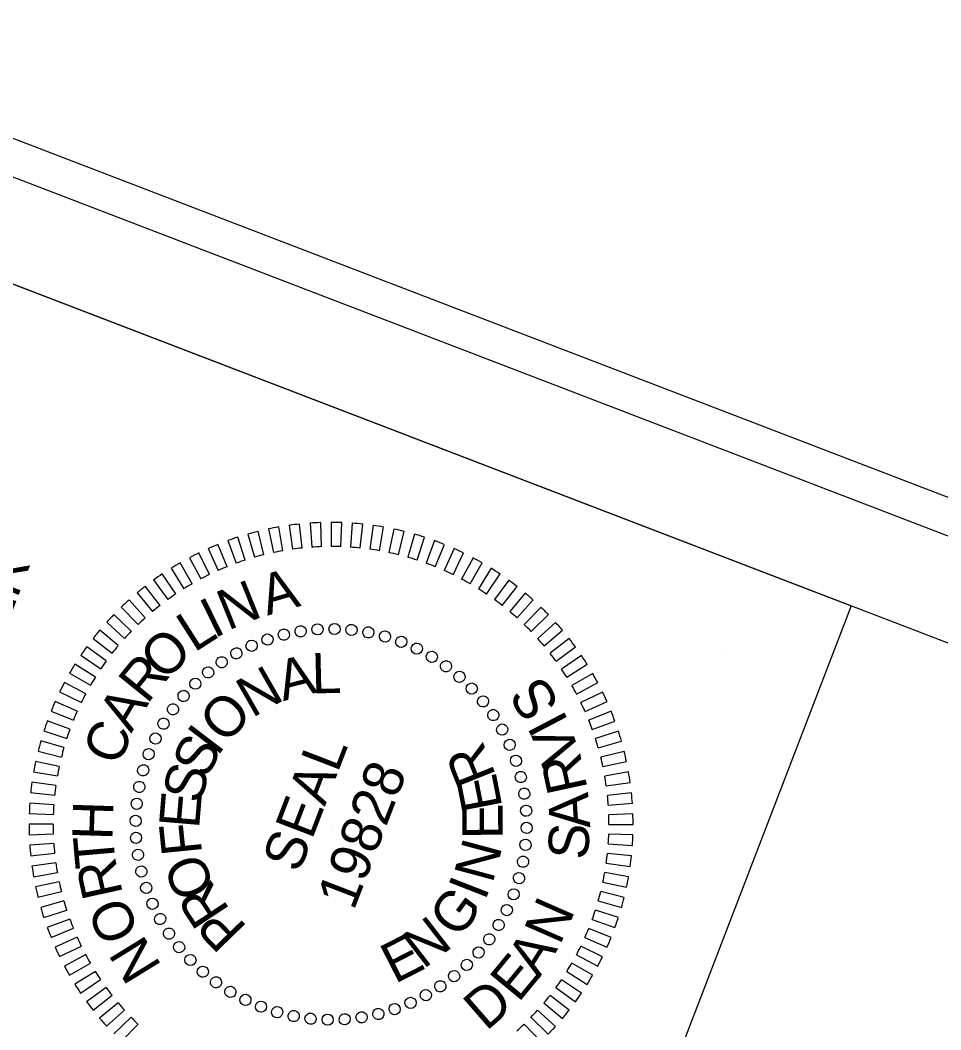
# Model space of a CAD drawing. Extents: x 1015221 to 1064345, y 619216 to 647967.
# Drawn here: x 1034182 to 1035103, y 641647 to 642657 of the extents above; entities that cross this region are included whole.
import ezdxf

# ---------------------------------------------------------------- set-up
doc = ezdxf.new("R2010")
doc.units = 0
for name, color, linetype in [('Scratch_Level_0', 7, 'Continuous'), ('Sheet PE Seal Cell', 7, 'Continuous'), ('Sheet Plan CELL', 7, 'Continuous'), ('Sheet Plot Border Inside CELL', 7, 'Continuous'), ('Sheet Plot Border Outside CELL', 7, 'Continuous')]:
    doc.layers.add(name, color=color, linetype=linetype)

msp = doc.modelspace()

# ---------------------------------------------------------------- linework, layer by layer
at = {"layer": 'Scratch_Level_0'}
for p, q in [((1034883.3, 642026.4), (1034883.3, 642026.4)), ((1034492.9, 641852.7), (1034492.9, 641852.7))]:
    msp.add_line(p, q, dxfattribs=at)
at = {"layer": 'Sheet PE Seal Cell'}
for p, q in [((1034444.7, 642126.5), (1034440.6, 642150.3)), ((1034451, 642151.9), (1034454.3, 642128)), ((1034464, 642129.2), (1034461.4, 642153.2)), ((1034471.9, 642154.1), (1034473.6, 642130)), ((1034483.3, 642130.5), (1034482.5, 642154.7)), ((1034493, 642154.9), (1034493, 642130.7)), ((1034502.7, 642130.5), (1034503.6, 642154.7)), ((1034514.1, 642154.1), (1034512.4, 642130)), ((1034522.1, 642129.2), (1034524.6, 642153.2)), ((1034535.1, 642151.9), (1034531.7, 642128)), ((1034541.3, 642126.5), (1034545.5, 642150.3)), ((1034407.1, 642117.1), (1034399.6, 642140.1)), ((1034409.7, 642143.2), (1034416.4, 642119.9)), ((1034425.8, 642122.5), (1034419.9, 642145.9)), ((1034430.2, 642148.3), (1034435.2, 642124.6)), ((1034555.8, 642148.2), (1034550.8, 642124.6)), ((1034560.3, 642122.4), (1034566.1, 642145.9)), ((1034576.3, 642143.1), (1034569.6, 642119.9)), ((1034578.9, 642117.1), (1034586.4, 642140)), ((1034388.9, 642110.5), (1034379.8, 642132.9)), ((1034389.7, 642136.7), (1034397.9, 642114)), ((1034596.4, 642136.6), (1034588.1, 642113.9)), ((1034597.1, 642110.4), (1034606.2, 642132.8)), ((1034351.2, 642119.5), (1034362.5, 642098.2)), ((1034371.2, 642102.6), (1034360.6, 642124.3)), ((1034370.1, 642128.8), (1034379.9, 642106.7)), ((1034615.9, 642128.7), (1034606.1, 642106.6)), ((1034614.9, 642102.5), (1034625.5, 642124.2)), ((1034634.9, 642119.5), (1034623.5, 642098.1)), ((1034332.9, 642109), (1034345.7, 642088.5)), ((1034354, 642093.5), (1034341.9, 642114.4)), ((1034632, 642093.4), (1034644.1, 642114.3)), ((1034653.1, 642108.9), (1034640.3, 642088.4)), ((1034337.6, 642083.2), (1034324, 642103.3)), ((1034648.4, 642083.1), (1034662, 642103.2)), ((1034321.9, 642071.8), (1034307, 642090.9)), ((1034315.4, 642097.2), (1034329.6, 642077.7)), ((1034670.6, 642097.1), (1034656.4, 642077.6)), ((1034664.1, 642071.7), (1034679, 642090.8)), ((1034298.8, 642084.2), (1034314.3, 642065.7)), ((1034687.2, 642084.1), (1034671.7, 642065.6)), ((1034283.1, 642070.1), (1034299.9, 642052.7)), ((1034307, 642059.3), (1034290.8, 642077.3)), ((1034679, 642059.2), (1034695.2, 642077.2)), ((1034702.9, 642070), (1034686.1, 642052.6)), ((1034293, 642045.9), (1034275.6, 642062.7)), ((1034692.9, 642045.8), (1034710.3, 642062.5)), ((1034268.5, 642055), (1034286.4, 642038.8)), ((1034496.3, 642048.5), (1034496.3, 642048.5)), ((1034717.5, 642054.8), (1034699.6, 642038.7)), ((1034254.9, 642038.8), (1034273.9, 642023.9)), ((1034280, 642031.5), (1034261.5, 642047)), ((1034429.2, 642038), (1034429.2, 642038)), ((1034445.6, 642042.6), (1034445.6, 642042.6)), ((1034462.4, 642046.1), (1034462.4, 642046.1)), ((1034479.4, 642047.9), (1034479.4, 642047.9)), ((1034513.4, 642047.4), (1034513.4, 642047.4)), ((1034530.3, 642044.7), (1034530.3, 642044.7)), ((1034546.8, 642040.8), (1034546.8, 642040.8)), ((1034705.9, 642031.3), (1034724.4, 642046.9)), ((1034731.1, 642038.7), (1034712, 642023.8)), ((1034268.1, 642016.2), (1034248.5, 642030.4)), ((1034413.4, 642031.6), (1034413.4, 642031.6)), ((1034563.1, 642035.4), (1034563.1, 642035.4)), ((1034578.9, 642028.5), (1034578.9, 642028.5)), ((1034717.9, 642016), (1034737.4, 642030.2)), ((1034242.5, 642021.8), (1034262.5, 642008.2)), ((1034398, 642024.1), (1034398, 642024.1)), ((1034593.7, 642020.3), (1034593.7, 642020.3)), ((1034743.5, 642021.6), (1034723.4, 642008.1)), ((1034257.2, 642000.1), (1034236.7, 642012.9)), ((1034383.6, 642015), (1034383.6, 642015)), ((1034608.1, 642011), (1034608.1, 642011)), ((1034728.7, 642000), (1034749.2, 642012.8)), ((1034231.3, 642003.9), (1034252.2, 641991.8)), ((1034369.7, 642004.9), (1034369.7, 642004.9)), ((1034621.5, 642000.4), (1034621.5, 642000.4)), ((1034754.6, 642003.7), (1034733.7, 641991.6)), ((1034247.5, 641983.3), (1034226.2, 641994.6)), ((1034357, 641993.5), (1034357, 641993.5)), ((1034633.7, 641988.7), (1034633.7, 641988.7)), ((1034738.4, 641983.1), (1034759.8, 641994.5)), ((1034221.4, 641985.3), (1034243.1, 641974.6)), ((1034345.2, 641981.3), (1034345.2, 641981.3)), ((1034764.5, 641985.1), (1034742.8, 641974.5)), ((1034239, 641965.9), (1034216.9, 641975.7)), ((1034334.6, 641967.8), (1034334.6, 641967.8)), ((1034645.1, 641975.9), (1034645.1, 641975.9)), ((1034746.9, 641965.7), (1034769, 641975.5)), ((1034212.8, 641966), (1034235.2, 641956.9)), ((1034655.2, 641962), (1034655.2, 641962)), ((1034773.1, 641965.8), (1034750.7, 641956.8)), ((1034231.7, 641947.9), (1034209, 641956.1)), ((1034325.3, 641953.5), (1034325.3, 641953.5)), ((1034664.3, 641947.7), (1034664.3, 641947.7)), ((1034754.2, 641947.7), (1034776.9, 641956)), ((1034205.6, 641946.2), (1034228.6, 641938.7)), ((1034317.1, 641938.6), (1034317.1, 641938.6)), ((1034780.3, 641946), (1034757.3, 641938.5)), ((1034225.7, 641929.4), (1034202.5, 641936.1)), ((1034671.8, 641932.3), (1034671.8, 641932.3)), ((1034760.2, 641929.3), (1034783.4, 641935.9)), ((1034199.8, 641925.9), (1034223.2, 641920)), ((1034310.2, 641922.9), (1034310.2, 641922.9)), ((1034786.1, 641925.7), (1034762.7, 641919.9)), ((1034221, 641910.6), (1034197.4, 641915.6)), ((1034304.8, 641906.6), (1034304.8, 641906.6)), ((1034678.2, 641916.4), (1034678.2, 641916.4)), ((1034764.8, 641910.4), (1034788.5, 641915.4)), ((1034195.4, 641905.3), (1034219.2, 641901.1)), ((1034682.8, 641900.1), (1034682.8, 641900.1)), ((1034790.5, 641905.1), (1034766.7, 641900.9)), ((1034217.7, 641891.5), (1034193.7, 641894.9)), ((1034301, 641890.1), (1034301, 641890.1)), ((1034768.2, 641891.3), (1034792.2, 641894.7)), ((1034192.4, 641884.4), (1034216.5, 641881.9)), ((1034686.3, 641883.2), (1034686.3, 641883.2)), ((1034793.4, 641884.2), (1034769.4, 641881.7)), ((1034215.6, 641872.2), (1034191.5, 641873.9)), ((1034298.2, 641873.2), (1034298.2, 641873.2)), ((1034688.2, 641866.3), (1034688.2, 641866.3)), ((1034770.2, 641872), (1034794.3, 641873.7)), ((1034191, 641863.4), (1034215.1, 641862.5)), ((1034297.1, 641856.1), (1034297.1, 641856.1)), ((1034794.9, 641863.2), (1034770.7, 641862.3)), ((1034215, 641852.8), (1034190.8, 641852.8)), ((1034688.8, 641849.3), (1034688.8, 641849.3)), ((1034770.9, 641852.6), (1034795.1, 641852.6)), ((1034191, 641842.3), (1034215.1, 641843.1)), ((1034297.7, 641839.2), (1034297.7, 641839.2)), ((1034794.9, 641842.1), (1034770.7, 641842.9)), ((1034215.6, 641833.4), (1034191.5, 641831.7)), ((1034687.6, 641832.2), (1034687.6, 641832.2)), ((1034770.2, 641833.2), (1034794.3, 641831.6)), ((1034192.4, 641821.2), (1034216.5, 641823.7)), ((1034299.5, 641822.2), (1034299.5, 641822.2)), ((1034793.4, 641821), (1034769.4, 641823.6)), ((1034217.7, 641814.1), (1034193.7, 641810.8)), ((1034684.9, 641815.3), (1034684.9, 641815.3)), ((1034768.2, 641813.9), (1034792.1, 641810.6)), ((1034195.4, 641800.3), (1034219.2, 641804.5)), ((1034303.1, 641805.4), (1034303.1, 641805.4)), ((1034681, 641798.8), (1034681, 641798.8)), ((1034790.5, 641800.2), (1034766.7, 641804.4)), ((1034221, 641795), (1034197.4, 641790)), ((1034199.7, 641779.7), (1034223.2, 641785.5)), ((1034307.7, 641789), (1034307.7, 641789)), ((1034786.1, 641779.5), (1034762.6, 641785.4)), ((1034764.8, 641794.8), (1034788.5, 641789.8)), ((1034225.7, 641776.2), (1034202.5, 641769.5)), ((1034675.6, 641782.5), (1034675.6, 641782.5)), ((1034760.1, 641776), (1034783.3, 641769.3)), ((1034205.5, 641759.4), (1034228.5, 641766.9)), ((1034314.1, 641773.2), (1034314.1, 641773.2)), ((1034668.7, 641766.8), (1034668.7, 641766.8)), ((1034780.3, 641759.3), (1034757.3, 641766.7)), ((1034231.7, 641757.7), (1034209, 641749.5)), ((1034321.6, 641757.8), (1034321.6, 641757.8)), ((1034754.1, 641757.6), (1034776.8, 641749.3)), ((1034212.8, 641739.6), (1034235.2, 641748.7)), ((1034660.5, 641752), (1034660.5, 641752)), ((1034773, 641739.4), (1034750.6, 641748.5)), ((1034239, 641739.7), (1034216.9, 641729.9)), ((1034330.7, 641743.4), (1034330.7, 641743.4)), ((1034651.3, 641737.6), (1034651.3, 641737.6)), ((1034746.8, 641739.6), (1034768.9, 641729.7)), ((1034221.3, 641720.3), (1034243.1, 641730.9)), ((1034340.8, 641729.5), (1034340.8, 641729.5)), ((1034764.5, 641720.2), (1034742.7, 641730.8)), ((1034247.5, 641722.3), (1034226.1, 641710.9)), ((1034352.2, 641716.8), (1034352.2, 641716.8)), ((1034640.7, 641724.1), (1034640.7, 641724.1)), ((1034738.3, 641722.1), (1034759.7, 641710.8)), ((1034231.2, 641701.7), (1034252.2, 641713.8)), ((1034257.2, 641705.5), (1034236.6, 641692.7)), ((1034364.3, 641705), (1034364.3, 641705)), ((1034628.9, 641711.9), (1034628.9, 641711.9)), ((1034728.6, 641705.3), (1034749.1, 641692.5)), ((1034754.6, 641701.6), (1034733.6, 641713.7)), ((1034242.4, 641683.8), (1034262.4, 641697.3)), ((1034616.1, 641700.5), (1034616.1, 641700.5)), ((1034743.4, 641683.7), (1034723.3, 641697.2)), ((1034268, 641689.4), (1034248.4, 641675.2)), ((1034377.8, 641694.4), (1034377.8, 641694.4)), ((1034392.2, 641685.1), (1034392.2, 641685.1)), ((1034602.2, 641690.4), (1034602.2, 641690.4)), ((1034717.8, 641689.3), (1034737.3, 641675)), ((1034254.8, 641666.8), (1034273.8, 641681.6)), ((1034407, 641676.9), (1034407, 641676.9)), ((1034587.9, 641681.3), (1034587.9, 641681.3)), ((1034731, 641666.6), (1034711.9, 641681.5)), ((1034279.9, 641674.1), (1034261.4, 641658.6)), ((1034268.3, 641650.6), (1034286.3, 641666.8)), ((1034422.7, 641670), (1034422.7, 641670)), ((1034439, 641664.6), (1034439, 641664.6)), ((1034556.6, 641667.4), (1034556.6, 641667.4)), ((1034572.5, 641673.9), (1034572.5, 641673.9)), ((1034717.4, 641650.5), (1034699.5, 641666.7)), ((1034705.8, 641674), (1034724.3, 641658.4)), ((1034292.9, 641659.7), (1034275.5, 641642.9)), ((1034455.5, 641660.8), (1034455.5, 641660.8)), ((1034472.4, 641658), (1034472.4, 641658)), ((1034489.5, 641656.9), (1034489.5, 641656.9)), ((1034506.5, 641657.5), (1034506.5, 641657.5)), ((1034523.5, 641659.3), (1034523.5, 641659.3)), ((1034540.3, 641662.9), (1034540.3, 641662.9)), ((1034692.8, 641659.6), (1034710.2, 641642.8)), ((1034283, 641635.4), (1034299.8, 641652.8)), ((1034702.8, 641635.3), (1034686, 641652.7))]:
    msp.add_line(p, q, dxfattribs=at)
for radius, start, end in [(302.1, 99.9829, 101.9829), (302.1, 95.9829, 97.9829), (302.1, 91.9829, 93.9829), (302.1, 87.9829, 89.9829), (302.1, 83.9829, 85.9829), (302.1, 79.9829, 81.9829), (302.1, 107.9829, 109.9829), (302.1, 103.9829, 105.9829), (302.1, 75.9829, 77.9829), (302.1, 71.9829, 73.9829), (302.1, 111.9829, 113.9829), (278, 95.9829, 97.9829), (278, 91.9829, 93.9829), (278, 87.9829, 89.9829), (278, 83.9829, 85.9829), (302.1, 67.9829, 69.9829), (302.1, 115.9829, 117.9829), (278, 103.9829, 105.9829), (278, 99.9829, 101.9829), (278, 79.9829, 81.9829), (278, 75.9829, 77.9829), (278, 71.9829, 73.9829), (302.1, 63.9829, 65.9829), (302.1, 59.9829, 61.9829), (302.1, 119.9829, 121.9829), (278, 111.9829, 113.9829), (278, 107.9829, 109.9829), (278, 67.9829, 69.9829), (302.1, 55.9829, 57.9829), (302.1, 123.9829, 125.9829), (278, 115.9829, 117.9829), (278, 63.9829, 65.9829), (302.1, 127.9829, 129.9829), (278, 119.9829, 121.9829), (278, 59.9829, 61.9829), (278, 55.9829, 57.9829), (302.1, 51.9829, 53.9829), (278, 123.9829, 125.9829), (302.1, 47.9829, 49.9829), (302.1, 131.9829, 133.9829), (278, 127.9829, 129.9829), (278, 51.9829, 53.9829), (302.1, 43.9829, 45.9829), (302.1, 135.9829, 137.9829), (278, 131.9829, 133.9829), (278, 47.9829, 49.9829), (278, 43.9829, 45.9829), (302.1, 39.9829, 41.9829), (302.1, 139.9829, 141.9829), (278, 135.9829, 137.9829), (278, 39.9829, 41.9829), (302.1, 35.9829, 37.9829), (302.1, 143.9829, 145.9829), (278, 139.9829, 141.9829), (278, 35.9829, 37.9829), (302.1, 31.9829, 33.9829), (302.1, 147.9829, 149.9829), (278, 143.9829, 145.9829), (278, 31.9829, 33.9829), (278, 147.9829, 149.9829), (302.1, 27.9829, 29.9829), (302.1, 151.9829, 153.9829), (278, 27.9829, 29.9829), (278, 151.9829, 153.9829), (302.1, 23.9829, 25.9829), (302.1, 155.9829, 157.9829), (278, 23.9829, 25.9829), (278, 155.9829, 157.9829), (302.1, 19.9829, 21.9829), (302.1, 159.9829, 161.9829), (278, 159.9829, 161.9829), (278, 19.9829, 21.9829), (278, 15.9829, 17.9829), (302.1, 15.9829, 17.9829), (302.1, 163.9829, 165.9829), (278, 163.9829, 165.9829), (278, 11.9829, 13.9829), (302.1, 11.9829, 13.9829), (302.1, 167.9829, 169.9829), (278, 167.9829, 169.9829), (278, 7.9829, 9.9829), (302.1, 7.9829, 9.9829), (302.1, 171.9829, 173.9829), (278, 171.9829, 173.9829), (278, 3.9829, 5.9829), (302.1, 3.9829, 5.9829), (302.1, 175.9829, 177.9829), (278, 175.9829, 177.9829), (278, 359.9829, 1.9829), (302.1, 359.9829, 1.9829), (302.1, 179.9829, 181.9829), (278, 179.9829, 181.9829), (278, 355.9829, 357.9829), (302.1, 355.9829, 357.9829), (302.1, 183.9829, 185.9829), (278, 183.9829, 185.9829), (278, 351.9829, 353.9829), (302.1, 351.9829, 353.9829), (302.1, 187.9829, 189.9829), (278, 187.9829, 189.9829), (278, 347.9829, 349.9829), (302.1, 347.9829, 349.9829), (302.1, 191.9829, 193.9829), (278, 191.9829, 193.9829), (278, 343.9829, 345.9829), (278, 195.9829, 197.9829), (302.1, 343.9829, 345.9829), (302.1, 195.9829, 197.9829), (278, 339.9829, 341.9829), (278, 199.9829, 201.9829), (302.1, 339.9829, 341.9829), (302.1, 199.9829, 201.9829), (278, 335.9829, 337.9829), (278, 203.9829, 205.9829), (302.1, 335.9829, 337.9829), (302.1, 203.9829, 205.9829), (278, 331.9829, 333.9829), (278, 207.9829, 209.9829), (302.1, 331.9829, 333.9829), (302.1, 207.9829, 209.9829), (278, 211.9829, 213.9829), (278, 327.9829, 329.9829), (278, 323.9829, 325.9829), (302.1, 327.9829, 329.9829), (302.1, 211.9829, 213.9829), (278, 215.9829, 217.9829), (302.1, 215.9829, 217.9829), (278, 319.9829, 321.9829), (302.1, 323.9829, 325.9829), (278, 219.9829, 221.9829), (278, 315.9829, 317.9829), (302.1, 319.9829, 321.9829), (302.1, 219.9829, 221.9829), (278, 223.9829, 225.9829), (278, 311.9829, 313.9829), (302.1, 315.9829, 317.9829)]:
    msp.add_arc((1034492.9, 641852.7), radius, start, end, dxfattribs=at)
for centre, major_axis in [((1034445.7, 642042.5), (-1.36, 5.45)), ((1034462.4, 642045.9), (-0.88, 5.55)), ((1034479.3, 642047.8), (-0.39, 5.6)), ((1034496.4, 642048.2), (0.1, 5.61)), ((1034513.4, 642047.2), (0.59, 5.58)), ((1034530.3, 642044.7), (1.07, 5.51)), ((1034429.3, 642037.6), (-1.83, 5.31)), ((1034546.9, 642040.7), (1.55, 5.4)), ((1034563.1, 642035.3), (2.01, 5.24)), ((1034398.2, 642023.8), (-2.72, 4.91)), ((1034413.4, 642031.4), (-2.28, 5.13)), ((1034578.7, 642028.5), (2.46, 5.05)), ((1034383.6, 642014.9), (-3.14, 4.66)), ((1034593.7, 642020.3), (2.89, 4.81)), ((1034369.9, 642004.7), (-3.53, 4.36)), ((1034607.9, 642010.9), (3.3, 4.54)), ((1034357.1, 641993.4), (-3.9, 4.04)), ((1034621.3, 642000.3), (3.68, 4.24)), ((1034633.6, 641988.5), (4.04, 3.9)), ((1034345.4, 641981.1), (-4.24, 3.68)), ((1034644.9, 641975.7), (4.36, 3.53)), ((1034334.8, 641967.7), (-4.54, 3.3)), ((1034655.1, 641962), (4.66, 3.14)), ((1034325.3, 641953.5), (-4.81, 2.89)), ((1034664, 641947.5), (4.91, 2.72)), ((1034317.2, 641938.5), (-5.05, 2.46)), ((1034671.6, 641932.2), (5.13, 2.28)), ((1034310.4, 641922.9), (-5.24, 2.01)), ((1034677.9, 641916.3), (5.31, 1.83)), ((1034305, 641906.7), (-5.4, 1.55)), ((1034682.7, 641900), (5.45, 1.36)), ((1034301, 641890.1), (-5.51, 1.07)), ((1034686.1, 641883.3), (5.55, 0.88)), ((1034298.5, 641873.2), (-5.58, 0.59)), ((1034688, 641866.3), (5.6, 0.39)), ((1034297.4, 641856.2), (-5.61, 0.1)), ((1034688.5, 641849.2), (5.61, -0.1)), ((1034297.8, 641839.1), (-5.6, -0.39)), ((1034687.4, 641832.2), (5.58, -0.59)), ((1034299.8, 641822.2), (-5.55, -0.88)), ((1034684.9, 641815.3), (5.51, -1.07)), ((1034303.2, 641805.5), (-5.45, -1.36)), ((1034308, 641789.1), (-5.31, -1.83)), ((1034680.9, 641798.8), (5.4, -1.55)), ((1034675.5, 641782.6), (5.24, -2.01)), ((1034314.3, 641773.2), (-5.13, -2.28)), ((1034668.7, 641766.9), (5.05, -2.46)), ((1034321.9, 641758), (-4.91, -2.72)), ((1034660.5, 641751.9), (4.81, -2.89)), ((1034330.8, 641743.4), (-4.66, -3.14)), ((1034340.9, 641729.7), (-4.36, -3.53)), ((1034651.1, 641737.7), (4.54, -3.3)), ((1034640.5, 641724.4), (4.24, -3.68)), ((1034352.2, 641716.9), (-4.04, -3.9)), ((1034628.7, 641712), (3.9, -4.04)), ((1034364.6, 641705.2), (-3.68, -4.24)), ((1034616, 641700.7), (3.53, -4.36)), ((1034377.9, 641694.5), (-3.3, -4.54)), ((1034602.2, 641690.6), (3.14, -4.66)), ((1034392.2, 641685.1), (-2.89, -4.81)), ((1034587.7, 641681.7), (2.72, -4.91)), ((1034407.2, 641677), (-2.46, -5.05)), ((1034422.8, 641670.2), (-2.01, -5.24)), ((1034572.4, 641674), (2.28, -5.13)), ((1034439, 641664.8), (-1.55, -5.4)), ((1034455.6, 641660.8), (-1.07, -5.51)), ((1034472.4, 641658.2), (-0.59, -5.58)), ((1034523.5, 641659.6), (0.88, -5.55)), ((1034540.2, 641663), (1.36, -5.45)), ((1034556.5, 641667.8), (1.83, -5.31)), ((1034489.5, 641657.2), (-0.1, -5.61)), ((1034506.5, 641657.6), (0.39, -5.6))]:
    msp.add_ellipse(centre, major_axis=major_axis, ratio=0.999708, dxfattribs=at)
at = {"layer": 'Sheet Plan CELL'}
for points in [[(1033986, 642465.8), (1029682.3, 631264.1), (1037523.5, 628251.5), (1041827.2, 639453.2)], [(1033886.1, 641646.8), (1034173.1, 642394), (1035013.3, 642071.2), (1034726.1, 641324.2)]]:
    msp.add_lwpolyline(points, close=True, dxfattribs=at)
at = {"layer": 'Sheet Plot Border Inside CELL'}
msp.add_lwpolyline([(1037101.7, 627098), (1041881.8, 639539.4), (1034003.2, 642566.3), (1029223.2, 630125)], close=True, dxfattribs=at)
at = {"layer": 'Sheet Plot Border Outside CELL'}
msp.add_lwpolyline([(1037213.8, 626943.6), (1042044, 639515.6), (1033866.8, 642657.3), (1029036.6, 630085.3)], close=True, dxfattribs=at)

# ---------------------------------------------------------------- texts
at = {"layer": 'Sheet PE Seal Cell'}
for s, height, rotation, p in [('A', 40.3, 16.3132, (1034429.1, 642061.4)), ('N', 40.3, 22.0232, (1034389.7, 642046.4)), ('I', 40.3, 26.2152, (1034375.8, 642038.3)), ('L', 40.3, 32.5718, (1034356, 642024.2)), ('O', 40.3, 43.555, (1034325.8, 641994.9)), ('R', 40.3, 50.9668, (1034308.8, 641972.2)), ('A', 40.3, 14.3165, (1034445, 641975.9)), ('L', 40.3, 1.3526, (1034473.8, 641983.6)), ('N', 40.3, 29.7677, (1034413.9, 641958.7)), ('S', 40.3, 121.8807, (1034722.7, 641972.8)), ('A', 40.3, 59.569, (1034293, 641943.3)), ('O', 40.3, 46.3198, (1034387, 641931.8)), ('I', 40.3, 117.6886, (1034730.9, 641955.7)), ('C', 40.3, 68.8206, (1034281.1, 641910)), ('I', 40.3, 52.6373, (1034378.9, 641919.7)), ('S', 40.3, 63.6032, (1034368.3, 641896.8)), ('V', 40.3, 109.6003, (1034743, 641921.2)), ('SEAL', 40.29, 68.9829, (1034460.8, 641802.9)), ('R', 40.3, 111.7456, (1034658.2, 641901.4)), ('R', 40.3, 102.1884, (1034749.7, 641888.3)), ('S', 40.3, 74.5691, (1034362.2, 641872.2)), ('19828', 40.29, 68.9829, (1034515.5, 641765.5)), ('E', 40.3, 101.0652, (1034664.4, 641869.9)), ('E', 40.3, 85.2496, (1034360.8, 641847.7)), ('A', 40.3, 93.586, (1034752.2, 641849.5)), ('H', 40.3, 88.2167, (1034274.1, 641836.4)), ('E', 40.3, 90.3847, (1034664.6, 641837.9)), ('F', 40.3, 95.8078, (1034364, 641823.5)), ('S', 40.3, 86.3095, (1034749.7, 641816.7)), ('T', 40.3, 95.0332, (1034277.6, 641810.5)), ('N', 40.3, 74.9335, (1034654.4, 641792.7)), ('R', 40.3, 102.4449, (1034284.8, 641783.1)), ('O', 40.3, 112.3599, (1034377.6, 641788)), ('R', 40.3, 123.5297, (1034392.3, 641766.9)), ('I', 40.3, 68.616, (1034646.8, 641775.3)), ('G', 40.3, 53.1648, (1034620.6, 641737.1)), ('O', 40.3, 113.4281, (1034301.9, 641744.7)), ('N', 40.3, 66.2637, (1034721.8, 641730.9)), ('P', 40.3, 134.2102, (1034410, 641749.7)), ('N', 40.3, 37.7136, (1034585.2, 641707.2)), ('N', 40.3, 121.6527, (1034324.1, 641710.7)), ('E', 40.3, 27.0331, (1034556.7, 641692.7)), ('A', 40.3, 57.6613, (1034701, 641698)), ('E', 40.3, 50.5741, (1034680.3, 641673.5)), ('D', 40.3, 41.0653, (1034648.1, 641645.1))]:
    msp.add_text(s, height=height, rotation=rotation, dxfattribs=at).set_placement(p)
at = {"layer": 'Sheet Plan CELL'}
msp.add_text('ENGINEER', height=40, rotation=68.9841, dxfattribs=at).set_placement((1034092.6, 641853.4))

doc.saveas('drawing.dxf')
